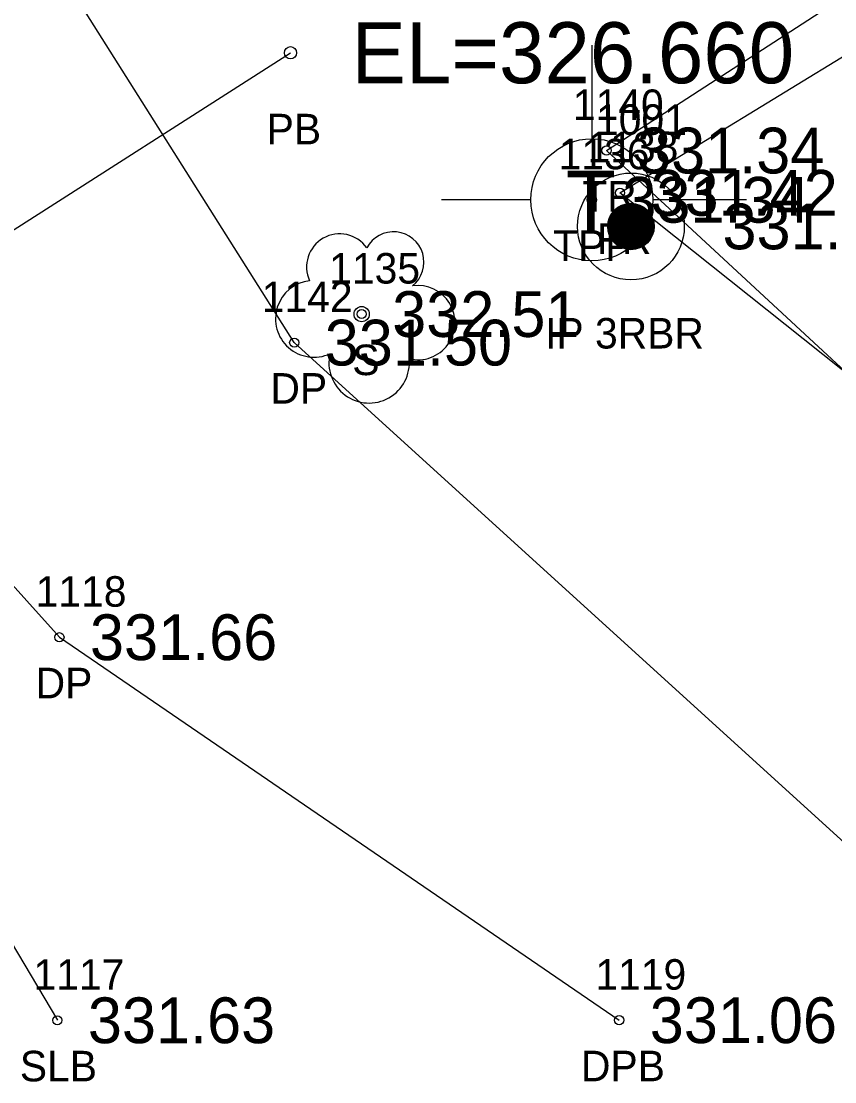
# Model space of a CAD drawing. Extents: x 2231119 to 2232595, y 1035731 to 1037094.
# Drawn here: x 2231711.37 to 2231738.02, y 1036465.83 to 1036500.58 of the extents above; entities that cross this region are included whole.
import ezdxf

# ---------------------------------------------------------------- set-up
doc = ezdxf.new("R2010")
doc.units = 0
for name, color, linetype in [('RD_EX_DR_Pipe', 7, 'Continuous'), ('RD_EX_DR_Pipe_txCode', 7, 'Continuous'), ('RD_EX_Driveway', 7, 'Continuous'), ('RD_EX_Driveway_txCode', 7, 'Continuous'), ('RD_EX_DV_Prop_txCode', 7, 'Continuous'), ('RD_EX_DV_PropPin', 7, 'Continuous'), ('RD_EX_Fence_Other', 7, 'Continuous'), ('RD_EX_Fence_Other_txCode', 7, 'Continuous'), ('RD_EX_TX_Driveway_ELEV', 7, 'Continuous'), ('RD_EX_TX_DV_Prop_ELEV', 7, 'Continuous'), ('RD_EX_TX_Fence_Other_ELEV', 7, 'Continuous'), ('RD_EX_TX_UT_ELEV', 7, 'Continuous'), ('RD_EX_TX_VEG_ELEV', 7, 'Continuous'), ('RD_EX_UT', 7, 'Continuous'), ('RD_EX_UT_txCode', 7, 'Continuous'), ('RD_EX_VEG', 7, 'Continuous'), ('RD_EX_VEG_txCode', 7, 'Continuous'), ('RD_SMD_Locator', 7, 'Continuous'), ('RD_TX_Pipe_ElevEX', 7, 'Continuous')]:
    doc.layers.add(name, color=color, linetype=linetype)

msp = doc.modelspace()

# ---------------------------------------------------------------- linework, layer by layer
at = {"layer": 'RD_EX_DR_Pipe'}
msp.add_line((2231694.987, 1036483.445), (2231720.193, 1036499.548), dxfattribs=at)
at = {"layer": 'RD_EX_Driveway'}
for points in [[(2231739.186, 1036472.896), (2231720.317, 1036490.052), (2231706.071, 1036512.594)], [(2231692.093, 1036503.238), (2231712.625, 1036480.399), (2231730.963, 1036467.852)]]:
    msp.add_lwpolyline(points, dxfattribs=at)
at = {"layer": 'RD_EX_DV_PropPin'}
for p, q in [((2231730.855, 1036493.276), (2231730.855, 1036494.441)), ((2231730.89, 1036493.249), (2231730.89, 1036494.468)), ((2231730.925, 1036493.224), (2231730.925, 1036494.493)), ((2231730.96, 1036493.202), (2231730.96, 1036494.515)), ((2231730.995, 1036493.183), (2231730.995, 1036494.534)), ((2231731.03, 1036493.166), (2231731.03, 1036494.551)), ((2231731.065, 1036493.151), (2231731.065, 1036494.566)), ((2231731.1, 1036493.138), (2231731.1, 1036494.579)), ((2231731.135, 1036493.127), (2231731.135, 1036494.59)), ((2231731.171, 1036493.118), (2231731.171, 1036494.599)), ((2231731.206, 1036493.11), (2231731.206, 1036494.607)), ((2231731.241, 1036493.105), (2231731.241, 1036494.612)), ((2231731.276, 1036493.101), (2231731.276, 1036494.616)), ((2231731.311, 1036493.098), (2231731.311, 1036494.619)), ((2231731.346, 1036493.097), (2231731.346, 1036494.62)), ((2231731.381, 1036493.098), (2231731.381, 1036494.619)), ((2231731.416, 1036493.101), (2231731.416, 1036494.616)), ((2231731.451, 1036493.105), (2231731.451, 1036494.612)), ((2231731.486, 1036493.11), (2231731.486, 1036494.607)), ((2231731.521, 1036493.118), (2231731.521, 1036494.599)), ((2231731.556, 1036493.127), (2231731.556, 1036494.59)), ((2231731.591, 1036493.138), (2231731.591, 1036494.579)), ((2231731.626, 1036493.151), (2231731.626, 1036494.566)), ((2231731.661, 1036493.166), (2231731.661, 1036494.551)), ((2231731.696, 1036493.183), (2231731.696, 1036494.534)), ((2231731.731, 1036493.202), (2231731.731, 1036494.515)), ((2231731.766, 1036493.224), (2231731.766, 1036494.493)), ((2231731.801, 1036493.249), (2231731.801, 1036494.468)), ((2231731.836, 1036493.276), (2231731.836, 1036494.441)), ((2231730.645, 1036493.561), (2231730.645, 1036494.156)), ((2231730.68, 1036493.489), (2231730.68, 1036494.228)), ((2231730.715, 1036493.432), (2231730.715, 1036494.285)), ((2231730.75, 1036493.384), (2231730.75, 1036494.333)), ((2231730.785, 1036493.343), (2231730.785, 1036494.374)), ((2231730.82, 1036493.308), (2231730.82, 1036494.409)), ((2231731.871, 1036493.308), (2231731.871, 1036494.409)), ((2231731.906, 1036493.343), (2231731.906, 1036494.374)), ((2231731.941, 1036493.384), (2231731.941, 1036494.333)), ((2231731.976, 1036493.432), (2231731.976, 1036494.285)), ((2231732.011, 1036493.489), (2231732.011, 1036494.228)), ((2231732.046, 1036493.561), (2231732.046, 1036494.156)), ((2231730.61, 1036493.662), (2231730.61, 1036494.055)), ((2231732.081, 1036493.662), (2231732.081, 1036494.055))]:
    msp.add_line(p, q, dxfattribs=at)
for radius in [1.75, 0.761]:
    msp.add_circle((2231731.346, 1036493.858), radius, dxfattribs=at)
at = {"layer": 'RD_EX_Fence_Other'}
msp.add_lwpolyline([(2231742.824, 1036485.512), (2231730.988, 1036494.959), (2231789.882, 1036531.024), (2231876.814, 1036583.892), (2231964.372, 1036635.233), (2232046.176, 1036684.795), (2232133.572, 1036734.398), (2232210.599, 1036793.489), (2232301.782, 1036835.026)], dxfattribs=at)
at = {"layer": 'RD_EX_UT'}
for p, q in [((2231730.066, 1036499.801), (2231730.066, 1036496.731)), ((2231725.136, 1036494.746), (2231728.066, 1036494.746)), ((2231732.066, 1036494.746), (2231735.136, 1036494.746))]:
    msp.add_line(p, q, dxfattribs=at)
msp.add_circle((2231730.066, 1036494.731), 2, dxfattribs=at)
at = {"layer": 'RD_EX_VEG'}
msp.add_line((2231704.106, 1036482.087), (2231712.557, 1036467.849), dxfattribs=at)
msp.add_lwpolyline([(2231753.591, 1036474.982), (2231730.547, 1036496.345), (2231788.451, 1036533.865), (2231871.454, 1036588.786), (2231958.943, 1036639.514), (2232040.643, 1036687.925), (2232130.591, 1036740.479), (2232213.065, 1036784.391), (2232299.538, 1036835.553)], dxfattribs=at)
msp.add_circle((2231722.526, 1036490.987), 0.25, dxfattribs=at)
for centre, radius, start, end in [((2231721.805, 1036492.534), 1.084, 34.9763, 204.756), ((2231723.571, 1036492.689), 0.995, 308.7626, 152.0467), ((2231720.962, 1036490.831), 1.257, 96.4518, 294.734), ((2231724.365, 1036490.707), 1.218, 256.5667, 98.1046), ((2231722.771, 1036489.39), 1.318, 166.8827, 5.7589)]:
    msp.add_arc(centre, radius, start, end, dxfattribs=at)
at = {"layer": 'RD_SMD_Locator'}
for centre, radius in [((2231720.193, 1036499.548), 0.2), ((2231730.547, 1036496.345), 0.15), ((2231730.066, 1036494.731), 0.15), ((2231730.988, 1036494.959), 0.15), ((2231731.346, 1036493.858), 0.15), ((2231722.526, 1036490.987), 0.15), ((2231720.317, 1036490.052), 0.15), ((2231712.625, 1036480.399), 0.15), ((2231712.557, 1036467.849), 0.15), ((2231730.963, 1036467.852), 0.15)]:
    msp.add_circle(centre, radius, dxfattribs=at)

# ---------------------------------------------------------------- texts
at = {"layer": 'RD_EX_DR_Pipe_txCode'}
msp.add_text('PB', height=1, dxfattribs=at).set_placement((2231719.414, 1036496.548))
at = {"layer": 'RD_EX_Driveway_txCode'}
for s, p in [('1142', (2231719.254, 1036491.052)), ('DP', (2231719.538, 1036488.052)), ('1118', (2231711.846, 1036481.399)), ('DP', (2231711.846, 1036478.399)), ('1119', (2231730.183, 1036468.852)), ('DPB', (2231729.711, 1036465.852))]:
    msp.add_text(s, height=1, dxfattribs=at).set_placement(p)
at = {"layer": 'RD_EX_DV_Prop_txCode'}
for s, p in [('1001', (2231730.204, 1036496.859)), ('IP 3RBR', (2231728.535, 1036489.859))]:
    msp.add_text(s, height=1, dxfattribs=at).set_placement(p)
at = {"layer": 'RD_EX_Fence_Other_txCode'}
for s, p in [('1138', (2231729.925, 1036495.959)), ('FR', (2231730.232, 1036492.959))]:
    msp.add_text(s, height=1, dxfattribs=at).set_placement(p)
at = {"layer": 'RD_EX_TX_Driveway_ELEV'}
for s, p in [('331.50', (2231721.317, 1036489.302)), ('331.66', (2231713.625, 1036479.649)), ('331.06', (2231731.963, 1036467.102))]:
    msp.add_text(s, height=1.5, dxfattribs=at).set_placement(p)
at = {"layer": 'RD_EX_TX_DV_Prop_ELEV'}
msp.add_text('331.75', height=1.5, dxfattribs=at).set_placement((2231734.346, 1036493.109))
at = {"layer": 'RD_EX_TX_Fence_Other_ELEV'}
msp.add_text('331.42', height=1.5, dxfattribs=at).set_placement((2231731.988, 1036494.209))
at = {"layer": 'RD_EX_TX_UT_ELEV'}
msp.add_text('331.34', height=1.5, dxfattribs=at).set_placement((2231731.066, 1036493.981))
at = {"layer": 'RD_EX_TX_VEG_ELEV'}
for s, p in [('331.34', (2231731.547, 1036495.595)), ('332.51', (2231723.526, 1036490.237)), ('331.63', (2231713.557, 1036467.099))]:
    msp.add_text(s, height=1.5, dxfattribs=at).set_placement(p)
at = {"layer": 'RD_EX_UT'}
msp.add_text('T', height=2, dxfattribs=at).set_placement((2231729.217, 1036493.684))
at = {"layer": 'RD_EX_UT_txCode'}
for s, p in [('1136', (2231728.979, 1036495.731)), ('TPP', (2231728.798, 1036492.731))]:
    msp.add_text(s, height=1, dxfattribs=at).set_placement(p)
at = {"layer": 'RD_EX_VEG_txCode'}
for s, p in [('1140', (2231729.445, 1036497.345)), ('TR', (2231729.752, 1036494.345)), ('1135', (2231721.463, 1036491.987)), ('S', (2231722.219, 1036488.987)), ('1117', (2231711.777, 1036468.849)), ('SLB', (2231711.328, 1036465.849))]:
    msp.add_text(s, height=1, dxfattribs=at).set_placement(p)
at = {"layer": 'RD_TX_Pipe_ElevEX'}
msp.add_text('EL=326.660', height=2, dxfattribs=at).set_placement((2231722.193, 1036498.548))

doc.saveas('drawing.dxf')
